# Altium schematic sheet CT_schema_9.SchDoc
size 147 x 119 mm
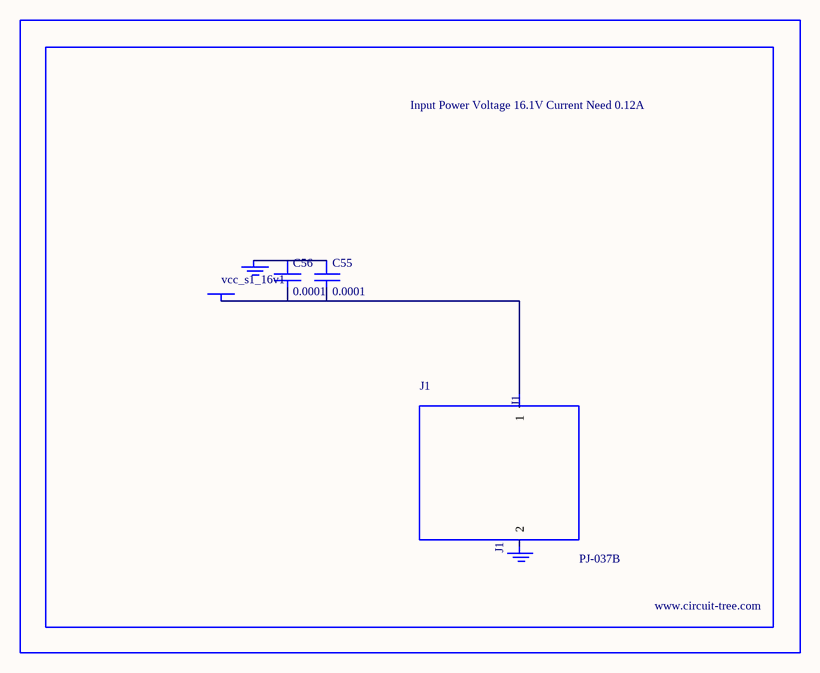
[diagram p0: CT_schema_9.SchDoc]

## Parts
BORDER8  (no value)
C55  0.0001  [EXV-9H]
C56  0.0001  [EXV-9H]
GND_INSTANCE_8_0  (no value)
GND_INSTANCE_8_1  (no value)
J1  PJ-037B  [PJ-037B_PACKAGE]
POWER_INSTANCE_8_0  vcc_s1_16v1

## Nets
NetC55_1: C55.1 C56.1 GND_INSTANCE_8_0.0(GND)
NetC55_2: C55.2 C56.2 J1.1 POWER_INSTANCE_8_0.0(PWR)

Not connected (* = marked no-connect by the designer): GND_INSTANCE_8_1 0(GND); J1 2

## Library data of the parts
BORDER8 = BORDER_PAGE8
C55 C56 = EDK107M035A9HAA
GND_INSTANCE_8_0 GND_INSTANCE_8_1 = GND
POWER_INSTANCE_8_0 = PWR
